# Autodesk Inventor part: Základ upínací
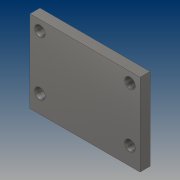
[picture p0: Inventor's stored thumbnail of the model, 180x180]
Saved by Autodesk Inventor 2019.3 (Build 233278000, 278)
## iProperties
Created: 2019-03
Part Number: Základ upínací
Material: Ocel, pozinkovaná
Document SubType Name: Modeling
Designer: B-hon
Density: 7.85 g/cm^3
Appearance: Pozinkovaná
Author: B-hon
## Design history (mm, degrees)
sketch "Náčrt1"
  geometry: L1 (-55, 4)-(55, 4); L2 (55, 4)-(55, -4); L3 (55, -4)-(-55, -4); L4 (-55, -4)-(-55, 4); L5 (-55, 4)-(55, -4); L6 (55, 4)-(-55, -4); L7 (-55, 78)-(55, 78); L8 (55, 78)-(55, -4); L9 (55, -4)-(-55, -4); L10 (-55, -4)-(-55, 78); 1 further point
  constraints: 20 end point, 4 parallel, 2 horizontal, 2 midpoint, 2 perpendicular
  dimensions: "d0" = 110 distance of L2.end L3.end; "d1" = 8 distance of L1.end L2.end; "d2" = 110 distance of L8.end L9.end; "d3" = 0 distance between parallel lines of L3 L9; "d4" = 82 distance of L9.end L7.start
extrude "Vysunutí1" new body sketch "Náčrt1" distance "d5" = 10; taper "d6" = 0 deg
sketch "Náčrt2"
  geometry: L1 (55, 78)-(-55, 78) reference; L2 (55, -4)-(55, 78) reference; L3 (-55, 78)-(55, 78); L4 (55, 78)-(55, 4); L5 (55, 4)-(-55, 4); L6 (-55, 4)-(-55, 78); L7 (-45, 14)-(45, 14); L8 (45, 14)-(45, 68); L9 (45, 68)-(-45, 68); L10 (-45, 68)-(-45, 14); 4 further points
  constraints: 16 end point, 4 coincident, 4 parallel, 2 perpendicular, 1 horizontal, 1 point on line, 3 other
  dimensions: "d18" = 74 distance of L3.end L4.end; "d19" = 10 distance between parallel lines of L5 L7
hole "Díra2" sketch "Náčrt2" at (-45, 68), (45, 68), (45, 14), (-45, 14) diameter "d20" = 10.5; stored, may be unused: countersink angle "d24" = 90 deg, drill point angle "d26" = 118 deg; dims "d21" = 35, "d22" = 10, "d23" = 2, "d25" = 40
node "Těleso1"
